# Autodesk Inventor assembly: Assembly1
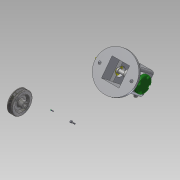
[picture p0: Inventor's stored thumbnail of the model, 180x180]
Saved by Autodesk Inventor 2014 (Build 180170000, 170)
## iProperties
Created: 2017-07
Part Number: Assembly1
Document SubType Name: Assembly
Designer: user
Author: user
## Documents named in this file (16)
- C:\Users\user\Desktop\470708V1004\OldVersions\Assembly1.iam
- C:\Users\user\Desktop\470708V1004\본체.ipt
- C:\Users\user\Desktop\470708V1004\V벨트풀리.ipt
- C:\Users\user\Desktop\470708V1004\고정핀 1.2 x  8.ipt
- C:\Users\user\Desktop\470708V1004\뒤커버.ipt
- C:\Users\user\Desktop\470708V1004\링크.ipt
- C:\Users\user\Desktop\470708V1004\멈춤나사 M3x8.ipt
- C:\Users\user\Desktop\470708V1004\베어링 12 x 32 x 10.ipt
- C:\Users\user\Desktop\470708V1004\볼트 M4 x 12.ipt
- C:\Users\user\Desktop\470708V1004\부시.ipt
- C:\Users\user\Desktop\470708V1004\슬라이드.ipt
- C:\Users\user\Desktop\470708V1004\앞커버.ipt
- C:\Users\user\Desktop\470708V1004\오일실 12 25 7.ipt
- C:\Users\user\Desktop\470708V1004\키 4 x 4 x 10.ipt
- C:\Users\user\Desktop\470708V1004\편심축.ipt
- C:\Users\user\Desktop\470708V1004\핀 5 x 18.ipt
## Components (3 placed, 3 different names)
1. V벨트풀리:1
2. 고정핀 1.2 x  8:1 — Mate:14
3. 핀 5 x 18:1 — Mate:14, Mate:15, Mate:16
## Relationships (3: Mate 3)
- Mate:14: 고정핀 1.2 x  8:1 ↔ 핀 5 x 18:1
- Mate:15: 핀 5 x 18:1
- Mate:16: 핀 5 x 18:1
